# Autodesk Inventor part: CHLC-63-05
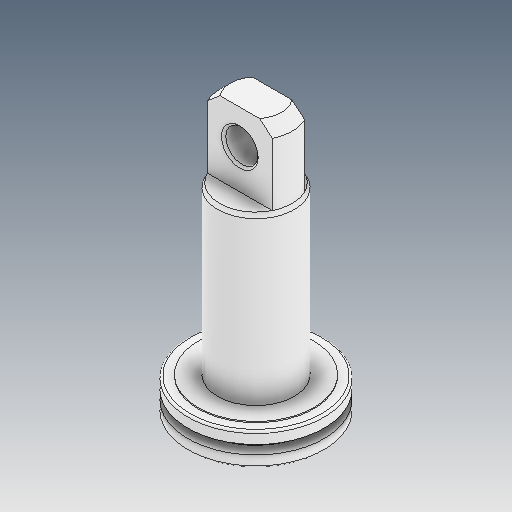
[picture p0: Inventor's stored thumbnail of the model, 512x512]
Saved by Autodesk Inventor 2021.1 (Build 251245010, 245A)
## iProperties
Created: 2021-05
Part Number: CHLC-63-05
Material: Ogólny
Document SubType Name: Modeling
Designer: user
Density: 1 g/cm^3
Appearance: Domyślna
Author: user
Revision Number: ÈÎºÎ
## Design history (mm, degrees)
feature "ÊäÈë1"
node "Bryła1"
